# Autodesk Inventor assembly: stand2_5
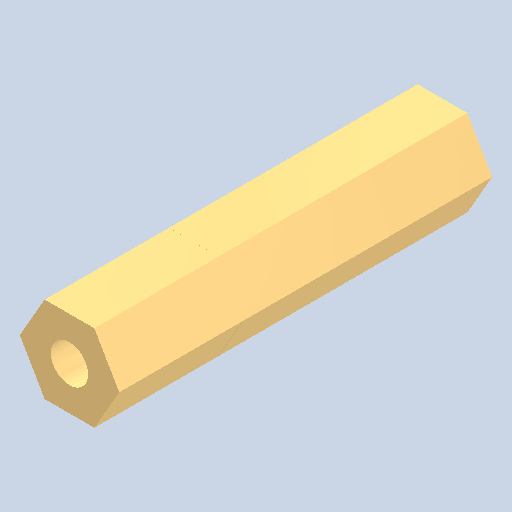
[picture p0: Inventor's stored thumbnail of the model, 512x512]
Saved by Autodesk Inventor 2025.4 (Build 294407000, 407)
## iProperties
Created: 2026-09
Part Number: stand2_5
Document SubType Name: Assembly
Designer: AdminForWorker
Title: stanofff v1
Author: AdminForWorker
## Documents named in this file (3)
- c:\worker\convert-fusion-r05-cosv3\tmp\job-1\19\temp\files\ca3d996b-dda0-445d-8bee-12a194174ca8\stanofff v1_2.iam
- c:\worker\convert-fusion-r05-cosv3\tmp\job-1\19\temp\files\ca3d996b-dda0-445d-8bee-12a194174ca8\M3-10 v1 (2).ipt
- c:\worker\convert-fusion-r05-cosv3\tmp\job-1\19\temp\files\ca3d996b-dda0-445d-8bee-12a194174ca8\M3-20 v1.ipt
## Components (2 placed, 2 different names)
1. M3-10 v1 (2):1
2. M3-20 v1:1
